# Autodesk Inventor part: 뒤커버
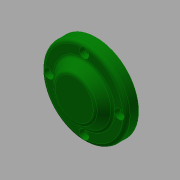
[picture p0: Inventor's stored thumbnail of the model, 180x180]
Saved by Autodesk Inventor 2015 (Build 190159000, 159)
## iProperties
Created: 2017-08
Part Number: 뒤커버
Material: 알루미늄 6061
Document SubType Name: Modeling
Designer: mduedu
Density: 1 g/cm^3
Appearance: 진녹색
Author: mduedu
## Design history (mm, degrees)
sketch "스케치1"
  geometry: C1 r 35 at (0, 0); 1 further point
  constraints: 1 centre point, 1 coincident
  dimensions: "d0" = 70 diameter of C1
extrude "돌출1" new body sketch "스케치1" distance "d1" = 10; taper "d2" = 0 deg
sketch "스케치2"
  geometry: C1 r 24 at (0, 0); 1 further point
  constraints: 1 centre point, 1 coincident
  dimensions: "d3" = 48 diameter of C1
node "작업 평면1"
sketch "스케치3"
  geometry: C1 r 17 at (0, 0); 1 further point
  constraints: 1 centre point, 1 coincident
  dimensions: "d5" = 34 diameter of C1
feature "로프트1" sketch "스케치3" dims "d6" = 0, "d7" = 90 deg, "d8" = 0, "d9" = 90 deg
sketch "스케치4"
  geometry: C1 r 24 at (0, 0) reference; 1 further point
extrude "돌출2" join sketch "스케치4" distance "d10" = 8; taper "d11" = 0 deg
hole "구멍1" diameter "d14" = 40; stored, may be unused: countersink angle "d18" = 90 deg, drill point angle "d20" = 0 deg; dims "d12" = 10, "d13" = 10, "d15" = 6, "d16" = 4, "d17" = 2, "d19" = 12
hole "구멍2" diameter "d23" = 34; stored, may be unused: countersink angle "d27" = 90 deg, drill point angle "d29" = 0 deg; dims "d24" = 6, "d25" = 4, "d26" = 2, "d28" = 6, "d62" = 10, "d63" = 10
chamfer "모따기1" distance "d39" = 1; stored, may be unused: second distance "d40" = 2, angle "d41" = 45 deg
fillet "모깎기1" dims "d42" = 0.3
fillet "모깎기2" dims "d43" = 3
sketch "스케치5" dims "d44" = 58
  geometry: 6 further points
  constraints: 2 vertical alignment, 1 coincident, 7 other
  dimensions: "d47" = 360 deg dimension on point (0, 0) point (0, 29) (derived)
sketch "스케치6" dims "d64" = 58 (derived)
  geometry: 6 further points
  constraints: 1 coincident, 1 vertical alignment, 6 other
hole "구멍4" sketch "스케치6" at (0, 29), (-29, 0), (29, 0), (0, -29) diameter "d49" = 4.5; stored, may be unused: countersink angle "d53" = 90 deg, drill point angle "d55" = 0 deg; dims "d50" = 6, "d51" = 8, "d52" = 4.6, "d54" = 8
fillet "모깎기3" dims "d56" = 3
fillet "모깎기4" dims "d57" = 3
fillet "모깎기5" dims "d58" = 3
node "솔리드1"
other parameters: "d4" = 8
